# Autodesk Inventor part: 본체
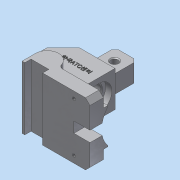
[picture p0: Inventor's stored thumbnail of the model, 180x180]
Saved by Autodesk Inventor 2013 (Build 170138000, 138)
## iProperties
Created: 2016-11
Part Number: 본체
Material: 알루미늄 6061
Document SubType Name: Modeling
Designer: dgall
Density: 2.71 g/cm^3
Mass: 462.813 g
Surface Area: 317.449 cm^2
Volume: 170.78 cm^3
Author: dgall
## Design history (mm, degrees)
sketch "스케치1"
  geometry: L1 (0, 0)-(0, 15); L2 (0, 0)-(3, 0); L3 (3, 0)-(3, 7); L4 (3, 7)-(23, 7); L5 (23, 7)-(23, 0); L6 (23, 0)-(76, 0); L7 (76, 0)-(76, 15); L8 (76, 15)-(26, 15); A1 r 13 centre (13, 15) between (26, 15) and (0, 15); 2 further points
  constraints: 16 end point, 4 parallel, 2 perpendicular, 2 point on circle, 1 centre point, 1 coincident, 1 collinear, 1 horizontal alignment, 1 midpoint, 1 point on line, 1 vertical, 1 vertical alignment
  dimensions: "d0" = 13 radius of A1; "d2" = 7 distance of L2.end L3.end; "d3" = 3 distance of L1.start L2.end; "d4" = 20 distance of L3.end L4.end; "d5" = 63 distance from line of L7 A1.centre; "d6" = 15 distance between parallel lines of L6 L8
extrude "돌출1" new body sketch "스케치1" distance "d7" = 70; taper "d8" = 0 deg
node "작업 평면1"
sketch "스케치2"
  geometry: L1 (-14, 12)-(-14, 42); L2 (-14, 42)-(4, 60); L3 (4, 60)-(14, 60); L4 (14, 60)-(14, 90); L5 (14, 90)-(39, 90); L6 (0, 0)-(0, 15) reference; L7 (26, 15)-(76, 15) reference; L8 (76, 15)-(76, 0) reference; L9 (76, 0)-(23, 0) reference; L10 (23, 0)-(23, 7) reference; L11 (23, 7)-(3, 7) reference; L12 (3, 7)-(3, 0) reference; L13 (3, 0)-(0, 0) reference; L14 (39, 90)-(39, 60); L15 (39, 60)-(44, 60); L16 (-14, 12)-(44, 12); L17 (44, 12)-(44, 60); A1 r 13 centre (13, 15) between (26, 15) and (0, 15) reference; 1 further point
  constraints: 18 end point, 3 parallel, 2 perpendicular, 2 vertical
  dimensions: "d9" = 12 distance from line of L13 L1.start; "d12" = 45 deg angle of L3 L2; "d13" = 18 distance from line of L2.end L1; "d17" = 25 distance of L4.end L5.end; "d21" = 90 distance between parallel lines of L9 L5; "d22" = 60 distance between parallel lines of L9 L15; "d23" = 5 distance of L14.end L15.end; "d25" = 90 distance between parallel lines of L8 L1; "d26" = 48 distance between parallel lines of L16 L3; "d97" = 58 distance between parallel lines of L17 L1
extrude "돌출2" join sketch "스케치2" stored distance "d27" = 40; taper "d28" = 0 deg
sketch "스케치3"
  geometry: L1 (0, 30)-(40, 30) reference; L2 (0, 0)-(0, 30) reference; L3 (0, 0)-(40, 0) reference; L4 (40, 30)-(40, 0) reference; L5 (10, 30)-(10, 0); L6 (30, 30)-(30, 0); L7 (30, 0)-(40, 0); L8 (30, 30)-(40, 30); L9 (40, 30)-(40, 0); L10 (10, 30)-(0, 30); L11 (0, 30)-(0, 0); L12 (0, 0)-(10, 0); 1 further point
  constraints: 16 end point, 4 collinear, 4 perpendicular, 4 point on line
  dimensions: "d29" = 10 distance between parallel lines of L5 L11; "d30" = 10 distance between parallel lines of L4 L6
extrude "돌출3" cut sketch "스케치3" distance "d31" = 40; taper "d32" = 0 deg
sketch "스케치4"
  geometry: L1 (15, -15)-(-55, -15) reference; C1 r 10 at (-20, 27); C2 r 14.5 at (-20, 27); 1 further point
  constraints: 2 centre point, 1 coincident, 1 midpoint, 1 vertical alignment
  dimensions: "d35" = 20 diameter of C1; "d37" = 29 diameter of C2; "d38" = 42 distance from line of L1 C1.centre
extrude "돌출4" cut sketch "스케치4" stored distance "d39" = 40; taper "d40" = 0 deg
extrude "돌출5" cut sketch "스케치4" distance "d41" = 7; taper "d42" = 0 deg
chamfer "모따기1" distance "d43" = 1; stored, may be unused: second distance "d44" = 2, angle "d45" = 45 deg
sketch "스케치6"
  geometry: L1 (-25, 30)-(0, 30) reference; L2 (-16, -60)-(37, -60) reference; C1 r 4 at (-12.5, 17); 2 further points
  constraints: 1 centre point, 1 midpoint, 1 vertical alignment
  dimensions: "d48" = 8 diameter of C1; "d50" = 77 distance from line of L2 C1.centre
extrude "돌출6" cut sketch "스케치6" stored distance "d51" = 7; taper "d52" = 0 deg
chamfer "모따기2" distance "d53" = 1; stored, may be unused: second distance "d54" = 2, angle "d55" = 45 deg
sketch "스케치7"
  geometry: L1 (0, 15)-(0, 0) reference; L2 (0, 0)-(-70, 0) reference; L3 (-41, 0)-(-41, 13.627); L4 (-29, 0)-(-29, 13.627); L5 (-41, 0)-(-29, 0); C1 r 14.5 at (-35, 42) reference; A1 r 29 centre (-35, 42) between (-41, 13.627) and (-29, 13.627); 1 further point
  constraints: 6 end point, 2 parallel, 2 perpendicular, 2 point on circle, 2 point on line, 1 centre point, 1 coincident, 1 collinear, 1 midpoint, 1 vertical alignment
  dimensions: "d56" = 12 distance of L3.start L4.start; "d58" = 58 diameter of A1
sketch "스케치8"
  geometry: L1 (0, 0)-(-70, 0) reference; L2 (-15, 15)-(-55, 15) reference; L3 (-15, 60)-(-15, 15) reference; L4 (-55, 60)-(-15, 60) reference; L5 (-55, 15)-(-55, 60) reference; L6 (-55, 20)-(-55, 0); L7 (-55, 20)-(-15, 20); L8 (-15, 20)-(-15, 0); C1 r 14.5 at (-35, 42) reference
  constraints: 6 end point, 3 perpendicular, 2 point on line, 2 vertical alignment
  dimensions: "d59" = 20 distance of L6.start L6.end
extrude "돌출7" join sketch "스케치8" stored distance "d61" = 0; taper "d62" = 0 deg
extrude "돌출8" cut sketch "스케치7" distance "d63" = 18; taper "d64" = 0 deg
chamfer "모따기3" distance "d68" = 4; stored, may be unused: second distance "d69" = 2, angle "d70" = 45 deg
chamfer "모따기4" distance "d71" = 4; stored, may be unused: second distance "d72" = 2, angle "d73" = 45 deg
fillet "모깎기1" dims "d74" = 5
chamfer "모따기5" distance "d75" = 5; stored, may be unused: second distance "d76" = 2, angle "d77" = 45 deg
sketch "스케치10"
  geometry: L1 (0, 15)-(40.708, 15) reference; L2 (45.708, 10)-(45.708, 0) reference; L3 (45.708, -50)-(40.708, -55) reference; L4 (45.708, -40)-(45.708, -50) reference; L5 (45.708, -40)-(0, -40) reference; L6 (0, -55)-(0, -40) reference; L7 (40.708, -55)-(0, -55) reference; L8 (4.708, -10)-(4.708, -30) reference; L9 (4.708, -10)-(-12.292, -10) reference; L10 (-12.292, -30)-(-12.292, -10) reference; L11 (-12.292, -30)-(4.708, -30) reference; L12 (45.708, -38.894)-(27.708, -38.894) reference; L13 (27.708, -38.894)-(27.708, -1.106) reference; L14 (27.708, -1.106)-(45.708, -1.106) reference; L15 (45.708, 0)-(45.708, -1.106) reference; L16 (45.708, 0)-(13.708, 0) reference; L17 (13.708, -40)-(13.708, 0) reference; L18 (45.708, -40)-(13.708, -40) reference; L19 (45.708, -38.894)-(45.708, -40) reference; 3 further points
  dimensions: "d78" = 18 distance from line of L2 point (27.708, 7.5); "d79" = 18 distance from line of point (27.708, -47.5) L4; "d80" = 55 distance of point (27.708, -47.5) point (27.708, 7.5); "d81" = 7.5 distance from line of point (27.708, 7.5) L1
hole "구멍1" sketch "스케치10" at (27.708, 7.5), (27.708, -47.5) diameter "d82" = 3.459; stored, may be unused: countersink angle "d86" = 90 deg, drill point angle "d88" = 118 deg; dims "d83" = 6, "d84" = 4, "d85" = 2, "d87" = 8
sketch "스케치11"
  geometry: L1 (44, 20)-(44, 60) reference; L2 (44, 60)-(4, 60) reference; 2 further points
  constraints: 1 other
  dimensions: "d89" = 18 distance from line of point (19, 42) L2; "d90" = 25 distance from line of L1 point (19, 42)
feature "엠보싱1" sketch "스케치11" dims "d0" = 13, "d2" = 7, "d3" = 3, "d4" = 20, "d5" = 63, "d6" = 15, "d91" = 0.5, "d92" = 0
fillet "모깎기2" dims "d93" = 3
fillet "모깎기3" dims "d94" = 3
sketch "스케치12"
  geometry: L1 (0, 0)-(0, 7) reference; L2 (20, 0)-(0, 0) reference; L3 (20, 7)-(20, 0) reference; L4 (0, 7)-(20, 7) reference; L5 (0, 0)-(0, 7); L6 (20, 7)-(20, 0); L7 (0, 0)-(20, 0); L8 (20, 0)-(20, 7); L9 (0, 7)-(20, 7); L10 (20, 7)-(20, 0); L11 (20, 7)-(20, 0); L12 (20, 7)-(20, 0); L13 (20, 0)-(20, 7); 1 further point
  constraints: 18 end point, 9 collinear
extrude "돌출9" cut sketch "스케치12" stored distance "d95" = 18; taper "d96" = 0 deg
node "솔리드1"
node "투영된 루프1"
node "투영된 루프2"
node "투영된 루프3"
node "투영된 루프4"
node "투영된 루프5"
